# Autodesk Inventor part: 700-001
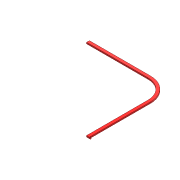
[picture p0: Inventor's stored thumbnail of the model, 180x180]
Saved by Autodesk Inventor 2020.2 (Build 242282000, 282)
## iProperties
Created: 2018-01
Part Number: 700-001
Material: Ogólne
Document SubType Name: Modeling
Designer: F.Stasiak
Density: 1 g/cm^3
Appearance: Jasnoczerwona
Manager: www.cadconsulting.pl
Company: Fabian Stasiak CAD Consulting
Author: F.Stasiak
Subject: Zbiór ćwiczeń. Autodesk Inventor 2020. Kurs podstawowy
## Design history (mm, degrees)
sketch "Szkic1"
  geometry: L1 (0, 0)-(2200, 0); L2 (3000, -800)-(3000, -3000); L3 (2900, -3000)-(2900, -800); L4 (2200, -100)-(0, -100); L5 (2900, -3000)-(3000, -3000); L6 (0, 0)-(0, -100); A1 r 800 centre (2200, -800) between (3000, -800) and (2200, 0); A2 r 700 centre (2200, -800) between (2900, -800) and (2200, -100)
  constraints: 12 end point, 4 point on circle, 3 perpendicular, 2 centre point, 2 horizontal, 2 tangent, 2 other
  dimensions: "d8" = 2200 distance of L1.start L1.end; "d9" = 100 distance between parallel lines of L2 L3; "d10" = 3000 distance between parallel lines of L5 L1; "d11" = 800 radius of A1
extrude "Wyciągnięcie proste1" new body sketch "Szkic1" distance "d2" = 50; taper "d3" = 0 deg
sketch "Szkic2"
  geometry: L1 (3000, -800)-(3000, -3000) reference; L2 (3000, -3000)-(3020, -3000); L3 (3020, -2960)-(3000, -2960); C1 r 11 at (3020, -2980); A1 r 20 centre (3020, -2980) between (3020, -3000) and (3020, -2960)
  constraints: 4 end point, 2 centre point, 2 point on circle, 2 tangent, 1 coincident, 1 horizontal, 1 perpendicular, 1 point on line
  dimensions: "d12" = 20 radius of A1; "d13" = 22 diameter of C1; "d14" = 20 distance from line of A1.centre L1
extrude "Wyciągnięcie proste2" join sketch "Szkic2" stored distance "d15" = 10; taper "d16" = 0 deg
node "Bryła1"
